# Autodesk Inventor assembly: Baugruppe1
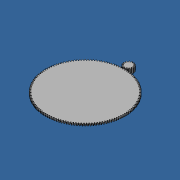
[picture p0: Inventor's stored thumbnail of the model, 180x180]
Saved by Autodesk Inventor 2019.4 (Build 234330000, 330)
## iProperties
Created: 2021-12
Part Number: Baugruppe1
Material: Generisch
Document SubType Name: Assembly
Mass: 38.9908 g
Surface Area: 72.805 cm^2
Volume: 4.96698 cm^3
Density: 7.85 g/cm^3
Masse: 0,04 kg
Fläche: 7280,5 mm^2
Volumen: 4966,98 mm^3
Abmasse: 65 mm x 72,78 mm x 4 mm
Keywords: =<Zeichnungsnummer><Korrektur>
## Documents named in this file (2)
- C:\Zahn\Baugruppe1.iam
- C:\Zahn\Baugruppe1\Konstruktions-Assistent\Stirnräder1.iam
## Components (1 placed, 1 different names)
1. Stirnräder:1 [sub-assembly]
